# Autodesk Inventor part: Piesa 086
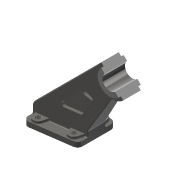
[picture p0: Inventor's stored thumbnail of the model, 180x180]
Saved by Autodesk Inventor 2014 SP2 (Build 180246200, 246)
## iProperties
Created: 2009-02
Part Number: Piesa 086
Document SubType Name: Modeling
Designer: Costel
Material: Steel, Cast
Density: 7.85 g/cm^3
Appearance: Steel - Cast
Author: Costel
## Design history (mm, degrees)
sketch "Sketch4"
  geometry: L1 (-23.125, 0)-(300.624, 0) reference; L2 (0, -39)-(0, 52) reference; L3 (0, 32.5)-(231.25, 0); L4 (0, -32.5)-(231.25, 0); L5 (8, 25.317)-(188.138, 0); L6 (188.138, 0)-(8, -25.317); L7 (8, 25.317)-(8, -25.317); L8 (0, 32.5)-(0, -32.5)
  constraints: 12 end point, 2 point on line, 1 collinear, 1 parallel, 1 symmetric about line, 1 other
  dimensions: "d21" = 6 distance between parallel lines of L5 L3; "d22" = 16 deg angle of L4 L3; "d23" = 8 distance between parallel lines of L7 L8; "d24" = 65 distance of L3.start L4.start
extrude "Extrusion4" new body sketch "Sketch4" distance "d25" = 167; taper "d26" = 0 deg
sketch "Sketch5"
  geometry: L1 (23.125, 0)-(-300.624, 0) reference; L2 (0, -16.7)-(0, 217.1) reference; L3 (0, 0)-(0, 30.255); L4 (0, 30.255)-(-127.373, 157.627); L5 (-100, 0)-(-100, 22); L6 (-100, 22)-(-146.855, 103.155); L7 (0, 0)-(-100, 0); A1 r 32 centre (-150, 135) between (-146.855, 103.155) and (-127.373, 157.627)
  constraints: 10 end point, 4 point on line, 2 point on circle, 1 centre point, 1 collinear, 1 parallel, 1 tangent
  dimensions: "d27" = 32 radius of A1; "d28" = 135 distance from line of L1 A1.centre; "d29" = 150 distance from line of L2 A1.centre; "d30" = 100 distance between parallel lines of L5 L2; "d32" = 22 distance of L5.start L5.end; "d33" = 60 deg angle of L1 L6; "d35" = 45 deg angle of L2 L4
extrude "Extrusion5" sketch "Sketch5" stored distance "d36" = 167; taper "d37" = 0 deg
sketch "Sketch6"
  geometry: L1 (14.685, 0)-(-190.911, 0) reference; L2 (0, -15.763)-(0, 204.916) reference; L3 (-8, 38.255)-(-127.373, 157.627) reference; L4 (-8, 0)-(-8, 38.255) reference; L5 (-100, 0)-(-8, 0) reference; L6 (-100, 22)-(-100, 0) reference; L7 (-146.855, 103.155)-(-100, 22) reference; L8 (-127.373, 157.627)-(0, 30.255) reference; L9 (-8, 26.941)-(-118.063, 137.004); L10 (-138.715, 105.056)-(-92, 24.144); L11 (-92, 24.144)-(-92, 0); A1 r 32 centre (-150, 135) between (-146.855, 103.155) and (-127.373, 157.627) reference
  constraints: 6 end point, 2 parallel, 2 point on circle, 2 point on line, 1 perpendicular
  dimensions: "d38" = 8 distance between parallel lines of L9 L3; "d39" = 8 distance between parallel lines of L7 L10 (= d38); "d40" = 8 distance between parallel lines of L6 L11 (= d39)
extrude "Extrusion6" join sketch "Sketch6" stored distance "d41" = 10; taper "d42" = 0 deg
sketch "Sketch7"
  geometry: L1 (-127.373, 157.627)-(0, 30.255) reference; L2 (-100, 22)-(-146.855, 103.155) reference; L3 (-127.373, 157.627)-(-172.627, 112.373); A1 r 32 centre (-150, 135) between (-138.715, 105.056) and (-118.063, 137.004) reference; A2 r 32 centre (-150, 135) between (-146.855, 103.155) and (-127.373, 157.627) reference; A3 r 32 centre (-150, 135) between (-172.627, 112.373) and (-127.373, 157.627)
  constraints: 2 end point, 2 point on circle, 1 centre point, 1 coincident, 1 perpendicular
extrude "Extrusion7" join sketch "Sketch7" stored distance "d43" = 36; taper "d44" = 0 deg
sketch "Sketch8"
  geometry: L1 (-127.373, 157.627)-(-172.627, 112.373) reference; A1 r 32 centre (-150, 135) between (-172.627, 112.373) and (-127.373, 157.627) reference; A2 r 32 centre (-150, 135) between (-172.627, 112.373) and (-127.373, 157.627) reference; A3 r 25 centre (-150, 135) between (-167.678, 117.322) and (-132.322, 152.678)
  constraints: 2 point on circle, 2 point on line, 1 centre point, 1 coincident
  dimensions: "d45" = 25 radius of A3
extrude "Extrusion8" join sketch "Sketch8" stored distance "d46" = 46; taper "d47" = 0 deg
fillet "Fillet1" dims "d48" = 18
fillet "Fillet2" dims "d49" = 15
fillet "Fillet3" dims "d50" = 5
fillet "Fillet4" dims "d51" = 7
fillet "Fillet5" dims "d52" = 10
sketch "Sketch9"
  geometry: L1 (132.322, 152.678)-(167.678, 117.322) reference; C1 r 15 at (150, 135); 1 further point
  constraints: 1 centre point, 1 coincident, 1 midpoint
  dimensions: "d53" = 15 radius of C1
extrude "Extrusion9" cut sketch "Sketch9" stored distance "d54" = 46; taper "d55" = 0 deg
sketch "Sketch10"
  geometry: L1 (17.263, 0)-(-224.416, 0) reference; L2 (-101.34, 24.321)-(-145.323, 100.502) reference; L3 (-127.373, 157.627)-(-4.393, 34.648) reference; L4 (-95.877, 91.192)-(-106.414, 85.109); L5 (-108.244, 78.279)-(-91.051, 48.5); L6 (-86.721, 46)-(-57.515, 46); L7 (-53.979, 54.536)-(-89.841, 90.398); A1 r 15 centre (-150, 135) between (-160.607, 124.393) and (-139.393, 145.607) reference; A2 r 5 centre (-57.515, 51) between (-57.515, 46) and (-53.979, 54.536); A3 r 5 centre (-93.377, 86.862) between (-89.841, 90.398) and (-95.877, 91.192); A4 r 5 centre (-103.914, 80.779) between (-106.414, 85.109) and (-108.244, 78.279); A5 r 5 centre (-86.721, 51) between (-91.051, 48.5) and (-86.721, 46)
  constraints: 8 end point, 8 point on circle, 8 tangent, 4 centre point, 3 equal radius, 3 parallel, 1 perpendicular
  dimensions: "d56" = 65 distance from line of A1.centre L4; "d57" = 46 distance between parallel lines of L1 L6; "d58" = 21 distance between parallel lines of L3 L7; "d59" = 21 distance between parallel lines of L2 L5; "d60" = 5 radius of A2
extrude "Extrusion10" cut sketch "Sketch10" stored distance "d61" = 46; taper "d62" = 0 deg
sketch "Sketch11"
  geometry: L1 (4.393, -31.883)-(4.393, 31.883) reference; L2 (4.393, -31.883)-(127.373, -14.599) reference; L3 (127.373, -14.599)-(127.373, 14.599) reference; L4 (127.373, 14.599)-(4.393, 31.883) reference; L5 (0, 32.5)-(0, -32.5) reference; L6 (-17.263, 0)-(224.416, 0) reference; L7 (11.392, 50.399)-(91.392, 39.156); L8 (11.392, -50.399)-(91.392, -39.156); L9 (0, 40.496)-(0, -40.496); L10 (100, 29.253)-(100, -29.253); L11 (100, -18.446)-(100, 18.446) reference; L12 (100, -18.446)-(0, -32.5) reference; L13 (0, -32.5)-(0, 32.5) reference; L14 (0, 32.5)-(100, 18.446) reference; L15 (92, -13.511)-(92, 13.511) reference; L16 (92, 13.511)-(8, 25.317) reference; L17 (8, 25.317)-(8, -25.317) reference; L18 (8, -25.317)-(92, -13.511) reference; A1 r 10 centre (10, 40.496) between (11.392, 50.399) and (0, 40.496); A2 r 10 centre (10, -40.496) between (0, -40.496) and (11.392, -50.399); A3 r 10 centre (90, -29.253) between (91.392, -39.156) and (100, -29.253); A4 r 10 centre (90, 29.253) between (100, 29.253) and (91.392, 39.156); 4 further points
  constraints: 8 end point, 8 point on circle, 8 point on line, 8 tangent, 4 centre point, 3 equal radius, 3 parallel, 2 symmetric about line, 1 collinear
  dimensions: "d63" = 100 distance between parallel lines of L10 L9; "d64" = 104 distance of point (0, 52) point (0, -52); "d65" = 10 radius of A1
extrude "Extrusion11" join sketch "Sketch11" distance "d66" = 10; taper "d67" = 0 deg
sketch "Sketch12"
  geometry: L1 (100, 18.446)-(0, 32.5) reference; L2 (100, 29.253)-(100, 18.446) reference; L3 (11.392, 50.399)-(91.392, 39.156) reference; L4 (0, 32.5)-(0, 40.496) reference; L5 (4.393, -31.883)-(4.393, 31.883) reference; L6 (4.393, -31.883)-(127.373, -14.599) reference; L7 (127.373, -14.599)-(127.373, 14.599) reference; L8 (127.373, 14.599)-(4.393, 31.883) reference; L9 (-37.233, 0)-(207.604, 0) reference; L10 (0, 40.496)-(0, -40.496) reference; L11 (8.341, 40.588)-(5.949, 31.664); L12 (27.659, 40.588)-(30.994, 28.144); L13 (72.341, 31.588)-(69.951, 22.669); L14 (91.659, 31.588)-(94.992, 19.15); L15 (18, 38)-(18, -38); L16 (82, 29)-(82, -29); L17 (8.341, -40.588)-(5.949, -31.664); L18 (27.659, -40.588)-(30.994, -28.144); L19 (72.341, -31.588)-(69.951, -22.669); L20 (91.659, -31.588)-(94.992, -19.15); L21 (5.949, -31.664)-(30.994, -28.144); L22 (69.951, -22.669)-(94.992, -19.15); L23 (69.951, 22.669)-(94.992, 19.15); L24 (5.949, 31.664)-(30.994, 28.144); A1 r 10 centre (90, 29.253) between (100, 29.253) and (91.392, 39.156) reference; A2 r 10 centre (10, 40.496) between (11.392, 50.399) and (0, 40.496) reference; A3 r 10 centre (18, 38) between (27.659, 40.588) and (8.341, 40.588); A4 r 10 centre (82, 29) between (91.659, 31.588) and (72.341, 31.588); A5 r 10 centre (18, -38) between (8.341, -40.588) and (27.659, -40.588); A6 r 10 centre (82, -29) between (72.341, -31.588) and (91.659, -31.588)
  constraints: 28 end point, 8 point on circle, 8 symmetric about line, 4 centre point, 4 collinear, 4 point on line, 4 tangent, 2 parallel, 1 equal radius, 4 other
  dimensions: "d68" = 10 radius of A3; "d69" = 18 distance from line of L10 L15.end; "d70" = 64 horizontal distance of L16.end L15.end; "d71" = 76 distance of L15.start L15.end; "d72" = 58 distance of L16.end L16.start; "d73" = 30 deg angle of L12 L11; "d74" = 30 deg angle of L14 L13 (= d73)
extrude "Extrusion12" join sketch "Sketch12" distance "d75" = 5; taper "d76" = 0 deg
sketch "Sketch13"
  geometry: L1 (5.949, 31.664)-(8.341, 40.588) reference; L2 (30.994, 28.144)-(5.949, 31.664) reference; L3 (27.659, 40.588)-(30.994, 28.144) reference; L4 (69.951, 22.669)-(72.341, 31.588) reference; L5 (94.992, 19.15)-(69.951, 22.669) reference; L6 (91.659, 31.588)-(94.992, 19.15) reference; L7 (69.951, -22.669)-(94.992, -19.15) reference; L8 (72.341, -31.588)-(69.951, -22.669) reference; L9 (94.992, -19.15)-(91.659, -31.588) reference; A1 r 10 centre (18, -38) between (8.341, -40.588) and (27.659, -40.588) reference; A2 r 10 centre (18, 38) between (27.659, 40.588) and (8.341, 40.588) reference; A3 r 10 centre (82, 29) between (91.659, 31.588) and (72.341, 31.588) reference; A4 r 10 centre (82, -29) between (72.341, -31.588) and (91.659, -31.588) reference
hole "Hole1" sketch "Sketch13" at (18, 38), (82, 29), (82, -29), (18, -38) diameter "d77" = 10; stored, may be unused: countersink angle "d81" = 90 deg, drill point angle "d83" = 118 deg; dims "d78" = 6, "d79" = 4, "d80" = 2, "d82" = 8
fillet "Fillet6" dims "d84" = 2
fillet "Fillet7" dims "d85" = 2
body "Solid1"
node "Projected Loop2"
node "Projected Loop3"
node "Projected Loop4"
node "Projected Loop5"
node "Projected Loop6"
node "Projected Loop7"
node "Projected Loop8"
node "Projected Loop9"
node "Projected Loop10"
